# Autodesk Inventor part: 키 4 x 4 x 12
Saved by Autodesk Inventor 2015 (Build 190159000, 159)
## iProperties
Created: 2025-08
Part Number: 키 4 x 4 x 12
Material: 일반
Document SubType Name: Modeling
Designer: user
Density: 1 g/cm^3
Appearance: 기본값
Author: user
Author: jhkim
Description: 키 및 해당 키홈
Creation Date: 2025-08-05
Sending System: Autodesk Inventor 2026
Preprocessor: ST-DEVELOPER v20.1
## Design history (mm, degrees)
node "키 4 x 4 x 121"
body "Solid1"
node "기준1"
